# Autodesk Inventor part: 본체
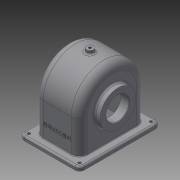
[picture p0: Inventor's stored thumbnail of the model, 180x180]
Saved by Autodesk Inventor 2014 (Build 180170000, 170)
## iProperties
Created: 2016-01
Part Number: 본체
Material: 일반
Document SubType Name: Modeling
Designer: USER
Density: 1 g/cm^3
Appearance: 기본값
Author: USER
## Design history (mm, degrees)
sketch "스케치1"
  geometry: L1 (-52, 70)-(52, 70); L2 (52, 70)-(52, -70); L3 (52, -70)-(-52, -70); L4 (-52, -70)-(-52, 70); L5 (-52, 70)-(52, -70); 2 further points
  constraints: 10 end point, 2 parallel, 1 coincident, 1 horizontal, 1 midpoint, 1 perpendicular
  dimensions: "d0" = 104 distance of L1.start L1.end; "d1" = 140 distance of L1.end L2.end
extrude "돌출1" new body sketch "스케치1" distance "d2" = 7; taper "d3" = 0 deg
fillet "모깎기1" dims "d4" = 8
sketch "스케치2"
  geometry: L1 (52, -62)-(52, 62) reference; L2 (-44, 62)-(44, 62); C1 r 2.5 at (-44, 62); C2 r 2.5 at (44, 62); 2 further points
  constraints: 2 centre point, 2 end point, 1 horizontal alignment, 1 midpoint, 1 perpendicular, 1 vertical alignment
  dimensions: "d5" = 5 diameter of C1; "d6" = 5 diameter of C2; "d7" = 88 distance of L2.start L2.end; "d8" = 62 distance from line of point (0, 0) L2
extrude "돌출2" cut sketch "스케치2" stored distance "d9" = 7; taper "d10" = 0 deg
fillet "모깎기2" dims "d11" = 3
node "작업 평면1"
sketch "스케치3"
  geometry: L1 (-38.5, 57)-(38.5, 57); L2 (38.5, 57)-(38.5, -57); L3 (38.5, -57)-(-38.5, -57); L4 (-38.5, -57)-(-38.5, 57); 3 further points
  constraints: 8 end point, 2 midpoint, 2 parallel, 1 horizontal, 1 horizontal alignment, 1 perpendicular, 1 vertical alignment
  dimensions: "d13" = 77 distance of L1.start L1.end; "d14" = 114 distance between parallel lines of L1 L3
extrude "돌출3" join sketch "스케치3" stored distance "d15" = 7; taper "d16" = 0 deg
sketch "스케치5"
  geometry: L1 (0, 0)-(0, 114) reference; L2 (0, 114)-(-57, 114) reference; L3 (0, 114)-(0, 0); A1 r 57 centre (0, 57) between (0, 0) and (0, 114); 1 further point
  constraints: 3 end point, 2 point on circle, 1 centre point, 1 midpoint, 1 perpendicular, 1 point on line
extrude "돌출4" join sketch "스케치5" distance "d17" = 77; taper "d18" = 0 deg
sketch "스케치6"
  geometry: L1 (-33.5, 51)-(33.5, 51); L2 (33.5, 51)-(33.5, -51); L3 (33.5, -51)-(-33.5, -51); L4 (-33.5, -51)-(-33.5, 51); 3 further points
  constraints: 8 end point, 2 midpoint, 2 parallel, 1 horizontal, 1 horizontal alignment, 1 perpendicular, 1 vertical alignment
  dimensions: "d19" = 67 distance of L1.start L1.end; "d20" = 102 distance between parallel lines of L3 L1
extrude "돌출5" cut sketch "스케치6" distance "d21" = 64; taper "d22" = 0 deg
sketch "스케치7"
  geometry: L1 (0, 102)-(64, 102) reference; L2 (64, 102)-(64, 0); A1 r 57 centre (64, 51) between (64, -6) and (64, 108) reference; A2 r 51 centre (64, 51) between (64, 0) and (64, 102); 1 further point
  constraints: 2 end point, 2 point on circle, 1 centre point, 1 perpendicular
  dimensions: "d23" = 6 radial gap between concentric circles of A2 A1; "d24" = 102 distance of L2.start L2.end
extrude "돌출6" cut sketch "스케치7" distance "d25" = 67; taper "d26" = 0 deg
fillet "모깎기3" dims "d27" = 14
fillet "모깎기4" dims "d28" = 9
fillet "모깎기5" dims "d29" = 1
node "작업 평면3"
  node "작업 평면2"
sketch "스케치9"
  geometry: C1 r 6 at (38.5, 0); 1 further point
  constraints: 1 centre point, 1 coincident
  dimensions: "d31" = 12 diameter of C1
extrude "돌출7" join sketch "스케치9" stored distance "d32" = 67; taper "d33" = 0 deg
fillet "모깎기6" dims "d34" = 3
sketch "스케치10"
  geometry: C1 r 6 at (0, 0) reference; C2 r 2.5 at (0, 0)
  constraints: 1 centre point, 1 coincident
  dimensions: "d35" = 5 diameter of C2
hole "구멍1" sketch "스케치10" at (0, 0) diameter "d36" = 4.459; stored, may be unused: countersink angle "d40" = 90 deg, drill point angle "d42" = 118 deg; dims "d37" = 20, "d38" = 4, "d39" = 2, "d41" = 30
sketch "스케치11"
  geometry: L1 (64, 62)-(64, -62) reference; C1 r 31 at (4, 0); 2 further points
  constraints: 1 centre point, 1 horizontal alignment, 1 midpoint
  dimensions: "d43" = 62 diameter of C1; "d44" = 60 distance from line of L1 C1.centre
extrude "돌출8" join sketch "스케치11" distance "d45" = 10; taper "d46" = 0 deg
sketch "스케치12"
  geometry: C1 r 31 at (0, 0) reference; C2 r 20 at (0, 0); 1 further point
  constraints: 1 centre point, 1 coincident
  dimensions: "d47" = 40 diameter of C2
extrude "돌출9" cut sketch "스케치12" stored distance "d48" = 10; taper "d49" = 0 deg
sketch "스케치13" dims "d51" = 48
  geometry: C1 r 20 at (0, 0) reference; C2 r 31 at (0, 0) reference; C3 r 1.5 at (-24, 0); 2 further points
  constraints: 2 horizontal alignment, 1 centre point, 1 coincident, 2 other
  dimensions: "d50" = 3 diameter of C3
hole "구멍2" sketch "스케치13" at (-24, 0) diameter "d52" = 2.459; stored, may be unused: countersink angle "d56" = 90 deg, drill point angle "d58" = 118 deg; dims "d53" = 6, "d54" = 4, "d55" = 2, "d57" = 8
chamfer "모따기1" distance "d62" = 1; stored, may be unused: second distance "d63" = 2, angle "d64" = 45 deg
fillet "모깎기7" dims "d65" = 3
sketch "스케치14"
  geometry: L1 (-33.5, 80)-(-33.5, 40) reference; L2 (-33.5, 60)-(74.437, 60); L3 (33.5, 64)-(33.5, 106) reference; L4 (33.5, 0)-(33.5, 64) reference; L5 (33.5, 99.747)-(19.5, 88); L6 (19.5, 88)-(19.5, 60); L7 (38.5, 107)-(38.5, 64) reference; L8 (19.5, 60)-(33.5, 60); L9 (33.5, 99.747)-(33.5, 60); 1 further point
  constraints: 10 end point, 4 point on line, 1 collinear, 1 midpoint, 1 parallel, 1 perpendicular
  dimensions: "d66" = 50 deg angle of L5 L6; "d68" = 56 diameter of L5.end L2; "d69" = 19 distance between parallel lines of L6 L7
revolve "회전1" sketch "스케치14" stored, may be unused: angle "d70" = 90 deg
sketch "스케치15"
  geometry: L1 (19.5, 32)-(19.5, 88) reference; L2 (38.5, 64)-(38.5, 8) reference; L3 (38.5, 107)-(38.5, 64) reference; L4 (19.5, 60)-(60.728, 60); L5 (19.5, 88)-(33.5, 99.747) reference; L6 (35.5, 94.899)-(38.5, 97.416); L7 (35.5, 94.899)-(35.5, 60); L8 (35.5, 60)-(38.5, 60); L9 (38.5, 97.416)-(38.5, 60); 1 further point
  constraints: 10 end point, 4 point on line, 2 perpendicular, 1 collinear, 1 midpoint, 1 parallel
  dimensions: "d71" = 5 distance between parallel lines of L6 L5; "d72" = 3 distance between parallel lines of L3 L7
revolve "회전2" sketch "스케치15" stored, may be unused: angle "d73" = 90 deg
fillet "모깎기8" dims "d74" = 3
fillet "모깎기9" dims "d75" = 3
sketch "스케치18"
  geometry: C1 r 33.5 at (0, 0) reference; C2 r 20 at (0, 0); 1 further point
  constraints: 1 centre point, 1 coincident
  dimensions: "d76" = 40 diameter of C2
extrude "돌출10" cut sketch "스케치18" distance "d77" = 16; taper "d78" = 0 deg
chamfer "모따기2" distance "d79" = 1; stored, may be unused: second distance "d80" = 2, angle "d81" = 45 deg
sketch "스케치19" dims "d83" = 56
  geometry: C1 r 33.5 at (0, 0) reference; C2 r 21 at (0, 0) reference; C3 r 1.5 at (28, 0); 2 further points
  constraints: 2 horizontal alignment, 1 centre point, 1 coincident, 2 other
  dimensions: "d82" = 3 diameter of C3
hole "구멍3" sketch "스케치19" at (28, 0) diameter "d84" = 2.459; stored, may be unused: countersink angle "d88" = 90 deg, drill point angle "d90" = 118 deg; dims "d85" = 7, "d86" = 4, "d87" = 2, "d89" = 9
sketch "스케치20"
  geometry: L1 (68.5, -64)-(-19.5, -64) reference; L2 (-14, 0)-(-14, -56) reference; 2 further points
  constraints: 1 other
  dimensions: "d94" = 30 distance from line of point (24.5, -34) L1; "d95" = 38.5 distance from line of point (24.5, -34) L2
extrude "돌출11" join sketch "스케치20" distance "d96" = 0.5; taper "d97" = 0 deg
node "솔리드1"
mirror "대칭1"
pattern_circular "원형 패턴1" dims angle "d60" = 360 deg
pattern_circular "원형 패턴2" dims angle "d92" = 360 deg
other parameters: "d12" = 64, "d30" = 6
